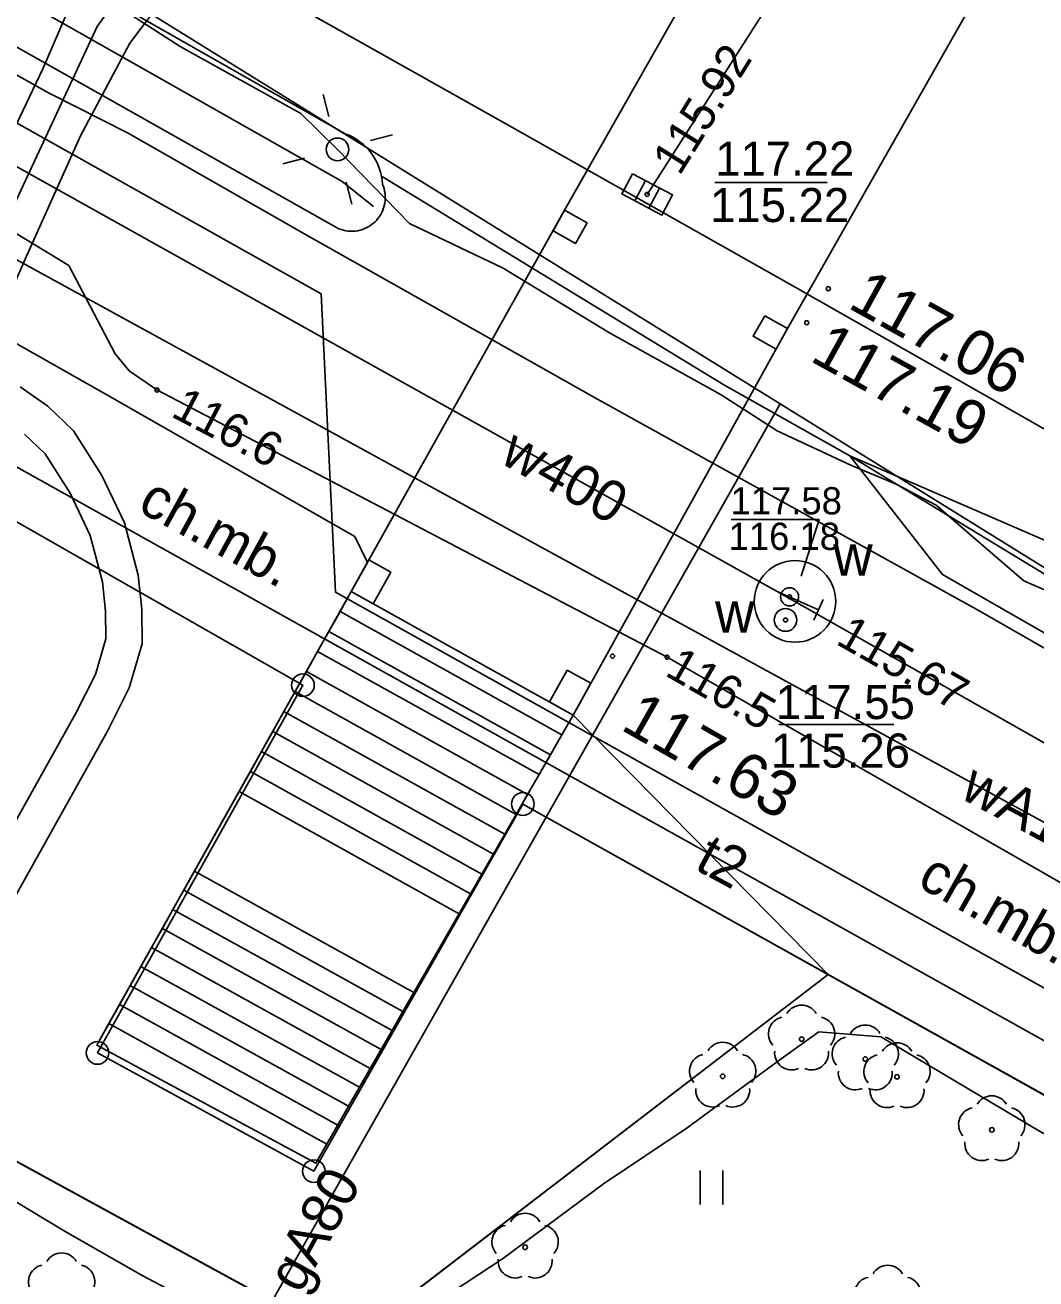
# Model space of a CAD drawing. Extents: x 6434771 to 6436222, y 5663454 to 5664782.
# Drawn here: x 6435235.8 to 6435258.09, y 5663843.93 to 5663871.57 of the extents above; entities that cross this region are included whole.
import ezdxf

# ---------------------------------------------------------------- set-up
doc = ezdxf.new("R2010")
doc.units = 0
for name, color, linetype in [('Warstwa 1', 7, 'Continuous'), ('Warstwa 10', 7, 'Continuous'), ('Warstwa 11', 7, 'Continuous'), ('Warstwa 12', 7, 'Continuous'), ('Warstwa 13', 7, 'Continuous'), ('Warstwa 14', 7, 'Continuous'), ('Warstwa 15', 7, 'Continuous'), ('Warstwa 2', 7, 'Continuous'), ('Warstwa 20', 7, 'Continuous'), ('Warstwa 25', 7, 'Continuous'), ('Warstwa 36', 7, 'Continuous'), ('Warstwa 4', 7, 'Continuous'), ('Warstwa 5', 7, 'Continuous'), ('Warstwa 6', 7, 'Continuous'), ('Warstwa 7', 7, 'Continuous'), ('Warstwa 8', 7, 'Continuous'), ('Warstwa 9', 7, 'Continuous')]:
    doc.layers.add(name, color=color, linetype=linetype)

msp = doc.modelspace()

# ---------------------------------------------------------------- linework, layer by layer
at = {"layer": 'Warstwa 1'}
for p, q in [((6435210.691, 5663874.851), (6435241.929, 5663857.022)), ((6435210.691, 5663874.851), (6435241.929, 5663857.022)), ((6435237.4, 5663848.916), (6435241.929, 5663857.022)), ((6435237.4, 5663848.916), (6435241.929, 5663857.022)), ((6435242.169, 5663846.309), (6435246.778, 5663854.403)), ((6435242.169, 5663846.309), (6435246.778, 5663854.403)), ((6435246.778, 5663854.403), (6435284.269, 5663833.48)), ((6435246.778, 5663854.403), (6435284.269, 5663833.48)), ((6435237.4, 5663848.916), (6435242.169, 5663846.309)), ((6435237.4, 5663848.916), (6435242.169, 5663846.309))]:
    msp.add_line(p, q, dxfattribs=at)
for points in [[(6435247.699, 5663867.491), (6435248.196, 5663867.212), (6435247.942, 5663866.759), (6435247.445, 5663867.037)], [(6435252.112, 5663865.166), (6435252.618, 5663864.883), (6435252.363, 5663864.429), (6435251.857, 5663864.713)], [(6435243.384, 5663859.783), (6435243.865, 5663859.516), (6435243.476, 5663858.817), (6435242.995, 5663859.084)], [(6435247.755, 5663857.355), (6435248.279, 5663857.063), (6435247.89, 5663856.364), (6435247.366, 5663856.655)]]:
    msp.add_lwpolyline(points, close=True, dxfattribs=at)
at = {"layer": 'Warstwa 10'}
for points in [[(6435276.336, 5663842.501), (6435260.05, 5663851.86), (6435249.96, 5663857.64), (6435238.71, 5663863.53), (6435238.1, 5663863.95), (6435237.79, 5663864.33), (6435236.77, 5663866.27), (6435229, 5663870.99), (6435224.85, 5663875.36), (6435224.07, 5663876.18), (6435215.14, 5663881.13), (6435208.14, 5663884.9), (6435192.12, 5663893.65), (6435170.67, 5663905.68), (6435152.15, 5663915.89), (6435146.79, 5663915.59), (6435128.02, 5663926.23), (6435125.23, 5663931.72), (6435111.04, 5663939.84), (6435099.552, 5663946.221)], [(6435276.398, 5663847.572), (6435270.914, 5663850.621), (6435269.128, 5663851.761), (6435267.523, 5663852.588), (6435261.727, 5663855.858), (6435256.855, 5663858.651), (6435248.36, 5663863.366), (6435242.1, 5663866.891), (6435238.077, 5663869.191), (6435236.318, 5663870.082), (6435231.153, 5663872.984), (6435227.254, 5663875.255), (6435219.004, 5663879.813), (6435214.473, 5663882.474), (6435208.6, 5663885.825), (6435204.743, 5663887.86), (6435202.556, 5663889.192), (6435198.825, 5663891.256), (6435191.441, 5663895.523), (6435189.466, 5663896.541), (6435185.427, 5663898.858)]]:
    msp.add_lwpolyline(points, dxfattribs=at)
for centre in [(6435241.929, 5663857.022), (6435241.929, 5663857.022), (6435246.778, 5663854.403), (6435246.778, 5663854.403), (6435237.4, 5663848.916), (6435237.4, 5663848.916), (6435242.169, 5663846.309), (6435242.169, 5663846.309)]:
    msp.add_circle(centre, 0.25, dxfattribs=at)
at = {"layer": 'Warstwa 11'}
for centre in [(6435252.926, 5663849.219), (6435254.33, 5663848.78), (6435251.186, 5663848.4), (6435255.03, 5663848.39), (6435257.12, 5663847.22), (6435246.829, 5663844.632)]:
    msp.add_circle(centre, 0.05, dxfattribs=at)
for centre, start, end in [((6435252.926, 5663849.594), 30.1471, 149.8529), ((6435252.569, 5663849.335), 102.1471, 221.8529), ((6435253.283, 5663849.335), 318.1471, 77.8529), ((6435254.33, 5663849.155), 30.1471, 149.8529), ((6435251.186, 5663848.775), 30.1471, 149.8529), ((6435253.973, 5663848.896), 102.1471, 221.8529), ((6435255.03, 5663848.765), 30.1471, 149.8529), ((6435254.687, 5663848.896), 318.1471, 77.8529), ((6435250.829, 5663848.516), 102.1471, 221.8529), ((6435251.543, 5663848.516), 318.1471, 77.8529), ((6435252.706, 5663848.916), 174.1471, 293.8529), ((6435253.146, 5663848.916), 246.1471, 5.8529), ((6435254.673, 5663848.506), 102.1471, 221.8529), ((6435255.387, 5663848.506), 318.1471, 77.8529), ((6435254.11, 5663848.477), 174.1471, 293.8529), ((6435254.55, 5663848.477), 246.1471, 5.8529), ((6435250.966, 5663848.097), 174.1471, 293.8529), ((6435251.406, 5663848.097), 246.1471, 5.8529), ((6435254.81, 5663848.087), 174.1471, 293.8529), ((6435255.25, 5663848.087), 246.1471, 5.8529), ((6435257.12, 5663847.595), 30.1471, 149.8529), ((6435256.763, 5663847.336), 102.1471, 221.8529), ((6435257.477, 5663847.336), 318.1471, 77.8529), ((6435256.9, 5663846.917), 174.1471, 293.8529), ((6435257.34, 5663846.917), 246.1471, 5.8529), ((6435246.829, 5663845.007), 30.1471, 149.8529), ((6435246.472, 5663844.748), 102.1471, 221.8529), ((6435247.186, 5663844.748), 318.1471, 77.8529), ((6435236.608, 5663844.131), 30.1471, 149.8529), ((6435236.251, 5663843.872), 102.1471, 221.8529), ((6435236.965, 5663843.872), 318.1471, 77.8529), ((6435246.609, 5663844.329), 174.1471, 293.8529), ((6435247.049, 5663844.329), 246.1471, 5.8529), ((6435254.826, 5663843.861), 30.1471, 149.8529), ((6435254.469, 5663843.602), 102.1471, 221.8529), ((6435255.183, 5663843.602), 318.1471, 77.8529)]:
    msp.add_arc(centre, 0.375, start, end, dxfattribs=at)
at = {"layer": 'Warstwa 12'}
for points in [[(6435276.296, 5663839.122), (6435202.248, 5663880.463), (6435193.528, 5663885.439), (6435193.106, 5663885.714), (6435192.653, 5663885.899), (6435159.975, 5663904.455), (6435111.809, 5663931.659), (6435087.394, 5663945.495), (6435086.953, 5663945.766), (6435086.601, 5663946.025), (6435086.024, 5663946.382)], [(6435107.26, 5663946.125), (6435127.986, 5663934.544), (6435149.124, 5663922.599), (6435165.622, 5663913.277), (6435237.784, 5663872.323), (6435252.455, 5663863.225), (6435276.408, 5663848.377)], [(6435246.313, 5663910.094), (6435245.72, 5663909.93), (6435240.9, 5663901.36), (6435226.24, 5663874.68), (6435242.33, 5663865.65), (6435242.65, 5663859.07), (6435272.24, 5663842.55), (6435276.308, 5663840.167)], [(6435256.631, 5663899.106), (6435254.109, 5663895.435), (6435253.432, 5663894.446), (6435252.842, 5663893.524), (6435250.72, 5663890.467), (6435247.918, 5663886.553), (6435245.206, 5663882.627), (6435241.482, 5663877.301), (6435239.483, 5663874.478), (6435237.391, 5663871.54), (6435235.32, 5663867.088), (6435232.38, 5663860.459), (6435228.304, 5663851.592), (6435226.059, 5663846.687), (6435233.662, 5663842.273), (6435239.222, 5663839.112), (6435239.979, 5663838.573), (6435240.755, 5663838.015), (6435243.432, 5663836.474), (6435248.386, 5663833.561), (6435249.655, 5663832.225)], [(6435223.924, 5663873.574), (6435225.447, 5663872.732), (6435231.141, 5663868.843), (6435252.104, 5663857.369), (6435275.75, 5663844.453)], [(6435237.986, 5663871.892), (6435239.219, 5663871.101), (6435241.885, 5663869.623), (6435242.692, 5663868.834), (6435244.278, 5663867.202), (6435246.346, 5663866.214), (6435248.688, 5663864.788), (6435251.155, 5663863.423), (6435252.387, 5663862.631), (6435254.024, 5663861.865), (6435255.012, 5663861.45), (6435255.89, 5663860.989), (6435256.658, 5663860.327), (6435257.826, 5663859.319), (6435258.506, 5663859.031), (6435259.805, 5663858.704), (6435260.919, 5663858.35)], [(6435232.54, 5663865.66), (6435234.09, 5663868.71), (6435234.89, 5663868.85), (6435252.389, 5663859.088), (6435252.78, 5663858.87), (6435276.372, 5663845.49)], [(6435233.809, 5663849.202), (6435237.617, 5663856.012), (6435238.098, 5663856.963), (6435238.387, 5663857.936), (6435238.377, 5663858.699), (6435238.298, 5663859.449), (6435237.993, 5663860.6), (6435237.497, 5663861.645), (6435236.869, 5663862.63), (6435236.301, 5663863.176), (6435235.694, 5663863.596)], [(6435224.443, 5663813.783), (6435252.455, 5663863.225)], [(6435235.793, 5663862.554), (6435236.245, 5663862.12), (6435236.795, 5663861.257), (6435237.239, 5663860.324), (6435237.508, 5663859.303), (6435237.577, 5663858.651), (6435237.585, 5663858.046), (6435237.352, 5663857.259), (6435236.911, 5663856.388), (6435233.111, 5663849.592)], [(6435252.39, 5663859.09), (6435253.3, 5663858.68)], [(6435235.049, 5663845.961), (6435236.683, 5663844.978), (6435238.401, 5663844.001), (6435240.622, 5663842.825), (6435242.5, 5663841.606), (6435243.785, 5663842.585), (6435244.632, 5663843.258), (6435246.33, 5663844.379), (6435248.554, 5663846.03), (6435250.401, 5663847.265), (6435252.476, 5663848.785), (6435253.306, 5663849.381), (6435254.67, 5663849.272), (6435258.169, 5663847.194), (6435259.919, 5663846.249), (6435260.953, 5663845.694), (6435263.079, 5663844.425), (6435264.783, 5663843.511), (6435266.88, 5663842.337), (6435270.04, 5663840.543), (6435272.099, 5663839.408), (6435273.316, 5663838.648), (6435274.936, 5663837.804), (6435276.27, 5663836.996)]]:
    msp.add_lwpolyline(points, dxfattribs=at)
msp.add_lwpolyline([(6435247.89, 5663856.364), (6435242.995, 5663859.084), (6435247.699, 5663867.491), (6435254.05, 5663878.668), (6435260.23, 5663889.971), (6435267.246, 5663902.216), (6435272.128, 5663899.576), (6435265.126, 5663887.191), (6435258.938, 5663876.018), (6435252.618, 5663864.883)], close=True, dxfattribs=at)
at = {"layer": 'Warstwa 14'}
for p, q in [((6435251.014, 5663868.103), (6435253.487, 5663868.103)), ((6435254.959, 5663856.158), (6435252.426, 5663856.158))]:
    msp.add_line(p, q, dxfattribs=at)
msp.add_lwpolyline([(6435252.916, 5663859.423), (6435253.311, 5663860.674), (6435251.374, 5663860.674)], dxfattribs=at)
for centre in [(6435249.521, 5663867.841), (6435249.521, 5663867.841), (6435238.71, 5663863.53), (6435252.66, 5663858.97), (6435252.57, 5663858.46), (6435252.57, 5663858.46), (6435249.96, 5663857.64)]:
    msp.add_circle(centre, 0.045, dxfattribs=at)
at = {"layer": 'Warstwa 15'}
msp.add_circle((6435252.78, 5663858.87), 0.9, dxfattribs=at)
at = {"layer": 'Warstwa 2'}
msp.add_lwpolyline([(6435276.282, 5663837.937), (6435253.515, 5663850.644), (6435242.925, 5663842.53), (6435233.878, 5663847.467), (6435235.268, 5663860.824), (6435230.444, 5663863.459), (6435224.879, 5663866.571), (6435218.959, 5663869.867), (6435212.182, 5663873.589), (6435210.31, 5663874.67)], dxfattribs=at)
msp.add_circle((6435242.692, 5663868.834), 0.25, dxfattribs=at)
at = {"layer": 'Warstwa 20'}
msp.add_line((6435253.403, 5663858.908), (6435253.197, 5663858.452), dxfattribs=at)
at = {"layer": 'Warstwa 25'}
for centre in [(6435253.515, 5663865.762), (6435253.039, 5663865.012), (6435248.756, 5663857.662)]:
    msp.add_circle(centre, 0.045, dxfattribs=at)
at = {"layer": 'Warstwa 36'}
for p, q in [((6435247.638, 5663855.926), (6435242.748, 5663858.644)), ((6435247.387, 5663855.488), (6435242.501, 5663858.203)), ((6435247.135, 5663855.05), (6435242.253, 5663857.763)), ((6435246.883, 5663854.612), (6435242.006, 5663857.323)), ((6435246.631, 5663854.174), (6435241.759, 5663856.882)), ((6435246.379, 5663853.735), (6435241.511, 5663856.441)), ((6435246.128, 5663853.297), (6435241.264, 5663856)), ((6435245.876, 5663852.859), (6435241.017, 5663855.56)), ((6435245.625, 5663852.421), (6435240.77, 5663855.119)), ((6435244.135, 5663849.828), (6435239.3, 5663852.501)), ((6435243.895, 5663849.411), (6435239.064, 5663852.081)), ((6435243.655, 5663848.994), (6435238.829, 5663851.661)), ((6435243.415, 5663848.576), (6435238.593, 5663851.242)), ((6435243.175, 5663848.159), (6435238.358, 5663850.822)), ((6435242.936, 5663847.742), (6435238.122, 5663850.402)), ((6435242.696, 5663847.324), (6435237.887, 5663849.983)), ((6435242.456, 5663846.906), (6435237.651, 5663849.563))]:
    msp.add_line(p, q, dxfattribs=at)
for points in [[(6435242.995, 5663859.084), (6435247.89, 5663856.364), (6435242.216, 5663846.489), (6435237.384, 5663849.087), (6435242.995, 5663859.084)], [(6435240.522, 5663854.679), (6435245.373, 5663851.983)], [(6435239.536, 5663852.921), (6435244.375, 5663850.246)]]:
    msp.add_lwpolyline(points, dxfattribs=at)
at = {"layer": 'Warstwa 4'}
for p, q in [((6435249.483, 5663868.144), (6435249.25, 5663867.702)), ((6435249.792, 5663867.98), (6435249.559, 5663867.538))]:
    msp.add_line(p, q, dxfattribs=at)
for points in [[(6435243.487, 5663867.574), (6435242.798, 5663868.127), (6435217.042, 5663882.709)], [(6435242.5, 5663869.559), (6435242.373, 5663870.043)], [(6435243.417, 5663869.026), (6435243.901, 5663869.153)], [(6435241.967, 5663868.642), (6435241.483, 5663868.515)], [(6435242.884, 5663868.109), (6435243.011, 5663867.625)], [(6435253.991, 5663862.077), (6435258.99, 5663859.046), (6435274.658, 5663850.446), (6435276.421, 5663849.465)]]:
    msp.add_lwpolyline(points, dxfattribs=at)
msp.add_lwpolyline([(6435249.196, 5663868.296), (6435250.08, 5663867.829), (6435249.846, 5663867.386), (6435248.962, 5663867.853)], close=True, dxfattribs=at)
for centre, radius in [((6435252.66, 5663858.97), 0.2), ((6435252.57, 5663858.46), 0.25)]:
    msp.add_circle(centre, radius, dxfattribs=at)
at = {"layer": 'Warstwa 5'}
for p, q in [((6435242.925, 5663842.53), (6435253.515, 5663850.644)), ((6435253.515, 5663850.644), (6435276.282, 5663837.937)), ((6435233.878, 5663847.467), (6435242.925, 5663842.53)), ((6435250.687, 5663845.572), (6435250.687, 5663846.322)), ((6435251.187, 5663845.572), (6435251.187, 5663846.322))]:
    msp.add_line(p, q, dxfattribs=at)
at = {"layer": 'Warstwa 6'}
for points in [[(6435069.683, 5663952.11), (6435199.169, 5663878.85), (6435199.759, 5663878.873), (6435200.658, 5663880.452), (6435202.784, 5663879.266), (6435210.691, 5663874.851), (6435241.929, 5663857.022), (6435237.4, 5663848.916), (6435242.169, 5663846.309), (6435246.778, 5663854.403), (6435284.269, 5663833.48)], [(6435220.804, 5663883.166), (6435221.429, 5663883.018), (6435221.994, 5663882.855), (6435222.535, 5663882.686), (6435223.026, 5663882.511), (6435223.647, 5663882.272), (6435226.004, 5663880.916), (6435234.22, 5663876.266), (6435240.311, 5663872.825), (6435246.65, 5663869.255), (6435252.784, 5663865.794), (6435268.113, 5663857.071), (6435276.455, 5663852.276)], [(6435557.624, 5663617.186), (6435560.245, 5663620.878), (6435595.767, 5663670.923), (6435531.111, 5663701.684), (6435473.15, 5663729.463), (6435470.997, 5663730.839), (6435385.94, 5663776.469), (6435383.505, 5663771.998), (6435381.775, 5663772.849), (6435379.415, 5663768.737), (6435374.588, 5663771.455), (6435379.471, 5663779.947), (6435341.096, 5663801.352), (6435284.269, 5663833.48), (6435246.778, 5663854.403), (6435242.169, 5663846.309), (6435237.4, 5663848.916), (6435241.929, 5663857.022), (6435210.691, 5663874.851), (6435202.784, 5663879.266), (6435199.977, 5663874.56), (6435180.355, 5663839.798)]]:
    msp.add_lwpolyline(points, dxfattribs=at)
for centre in [(6435249.521, 5663867.841), (6435252.66, 5663858.97), (6435252.57, 5663858.46)]:
    msp.add_circle(centre, 0.045, dxfattribs=at)
at = {"layer": 'Warstwa 7'}
msp.add_lwpolyline([(6435249.521, 5663867.841), (6435254.668, 5663875.889)], dxfattribs=at)
at = {"layer": 'Warstwa 8'}
for p, q in [((6435240.311, 5663872.825), (6435246.65, 5663869.255)), ((6435246.65, 5663869.255), (6435252.784, 5663865.794)), ((6435252.784, 5663865.794), (6435268.113, 5663857.071))]:
    msp.add_line(p, q, dxfattribs=at)
for points in [[(6435239.364, 5663872.838), (6435238.113, 5663871.174), (6435237.025, 5663869.134), (6435235.807, 5663866.415), (6435234.445, 5663863.333)], [(6435234.5, 5663867.073), (6435236.194, 5663870.608), (6435236.942, 5663872.353)]]:
    msp.add_lwpolyline(points, dxfattribs=at)
at = {"layer": 'Warstwa 9'}
for p, q in [((6435218.213, 5663883.2), (6435242.876, 5663869.171)), ((6435215.871, 5663882.218), (6435242.721, 5663867.083)), ((6435240.311, 5663872.825), (6435246.65, 5663869.255)), ((6435242.876, 5663869.171), (6435242.96, 5663869.136)), ((6435242.96, 5663869.136), (6435243.041, 5663869.095)), ((6435243.041, 5663869.095), (6435243.118, 5663869.048)), ((6435243.118, 5663869.048), (6435243.192, 5663868.995)), ((6435246.65, 5663869.255), (6435252.784, 5663865.794)), ((6435243.192, 5663868.995), (6435243.262, 5663868.938)), ((6435243.262, 5663868.938), (6435243.328, 5663868.875)), ((6435243.328, 5663868.875), (6435243.389, 5663868.808)), ((6435243.389, 5663868.808), (6435243.445, 5663868.737)), ((6435243.445, 5663868.737), (6435243.496, 5663868.662)), ((6435243.496, 5663868.662), (6435243.541, 5663868.583)), ((6435243.541, 5663868.583), (6435243.58, 5663868.501)), ((6435243.58, 5663868.501), (6435243.613, 5663868.417)), ((6435243.613, 5663868.417), (6435243.64, 5663868.33)), ((6435243.64, 5663868.33), (6435243.661, 5663868.242)), ((6435243.661, 5663868.242), (6435251.211, 5663863.643)), ((6435243.661, 5663868.242), (6435243.676, 5663868.153)), ((6435243.661, 5663868.242), (6435251.211, 5663863.643)), ((6435243.676, 5663868.153), (6435243.683, 5663868.062)), ((6435243.683, 5663868.062), (6435243.703, 5663868.013)), ((6435243.703, 5663868.013), (6435243.718, 5663867.962)), ((6435243.718, 5663867.962), (6435243.73, 5663867.91)), ((6435243.723, 5663867.594), (6435243.734, 5663867.646)), ((6435243.73, 5663867.91), (6435243.739, 5663867.858)), ((6435243.734, 5663867.646), (6435243.741, 5663867.699)), ((6435243.739, 5663867.858), (6435243.743, 5663867.805)), ((6435243.741, 5663867.699), (6435243.744, 5663867.752)), ((6435243.743, 5663867.805), (6435243.744, 5663867.752)), ((6435243.616, 5663867.352), (6435243.644, 5663867.397)), ((6435243.644, 5663867.397), (6435243.669, 5663867.444)), ((6435243.669, 5663867.444), (6435243.691, 5663867.493)), ((6435243.691, 5663867.493), (6435243.709, 5663867.543)), ((6435243.709, 5663867.543), (6435243.723, 5663867.594)), ((6435243.291, 5663867.086), (6435243.339, 5663867.109)), ((6435243.339, 5663867.109), (6435243.386, 5663867.135)), ((6435243.386, 5663867.135), (6435243.43, 5663867.164)), ((6435243.43, 5663867.164), (6435243.473, 5663867.196)), ((6435243.473, 5663867.196), (6435243.513, 5663867.231)), ((6435243.513, 5663867.231), (6435243.55, 5663867.269)), ((6435243.55, 5663867.269), (6435243.584, 5663867.309)), ((6435243.584, 5663867.309), (6435243.616, 5663867.352)), ((6435242.721, 5663867.083), (6435242.771, 5663867.065)), ((6435242.771, 5663867.065), (6435242.822, 5663867.05)), ((6435242.822, 5663867.05), (6435242.874, 5663867.039)), ((6435242.874, 5663867.039), (6435242.927, 5663867.032)), ((6435242.927, 5663867.032), (6435242.98, 5663867.028)), ((6435242.98, 5663867.028), (6435243.033, 5663867.029)), ((6435243.033, 5663867.029), (6435243.086, 5663867.033)), ((6435243.086, 5663867.033), (6435243.139, 5663867.04)), ((6435243.139, 5663867.04), (6435243.191, 5663867.052)), ((6435243.191, 5663867.052), (6435243.242, 5663867.067)), ((6435243.242, 5663867.067), (6435243.291, 5663867.086)), ((6435232.025, 5663866.569), (6435237.504, 5663863.481)), ((6435232.025, 5663866.569), (6435237.504, 5663863.481)), ((6435252.784, 5663865.794), (6435268.113, 5663857.071)), ((6435251.211, 5663863.643), (6435253.991, 5663862.077)), ((6435251.211, 5663863.643), (6435253.991, 5663862.077)), ((6435237.504, 5663863.481), (6435243.071, 5663860.303)), ((6435237.504, 5663863.481), (6435243.071, 5663860.303)), ((6435253.991, 5663862.077), (6435256.03, 5663859.462)), ((6435253.991, 5663862.077), (6435261.95, 5663858.63)), ((6435243.071, 5663860.303), (6435243.355, 5663859.727)), ((6435243.071, 5663860.303), (6435243.355, 5663859.727)), ((6435242.995, 5663859.084), (6435243.355, 5663859.727)), ((6435242.995, 5663859.084), (6435243.355, 5663859.727)), ((6435256.03, 5663859.462), (6435275.377, 5663848.338)), ((6435242.748, 5663858.644), (6435242.995, 5663859.084)), ((6435242.995, 5663859.084), (6435247.89, 5663856.364)), ((6435242.501, 5663858.203), (6435242.748, 5663858.644)), ((6435242.253, 5663857.763), (6435242.501, 5663858.203)), ((6435242.006, 5663857.323), (6435242.253, 5663857.763)), ((6435241.759, 5663856.882), (6435242.006, 5663857.323)), ((6435241.511, 5663856.441), (6435241.759, 5663856.882)), ((6435241.264, 5663856), (6435241.511, 5663856.441)), ((6435247.638, 5663855.926), (6435247.89, 5663856.364)), ((6435247.89, 5663856.364), (6435253.515, 5663850.644)), ((6435247.89, 5663856.364), (6435253.515, 5663850.644)), ((6435241.017, 5663855.56), (6435241.264, 5663856)), ((6435247.387, 5663855.488), (6435247.638, 5663855.926)), ((6435240.77, 5663855.119), (6435241.017, 5663855.56)), ((6435247.135, 5663855.05), (6435247.387, 5663855.488)), ((6435240.522, 5663854.679), (6435240.77, 5663855.119)), ((6435246.883, 5663854.612), (6435247.135, 5663855.05)), ((6435239.536, 5663852.921), (6435240.522, 5663854.679)), ((6435246.631, 5663854.174), (6435246.883, 5663854.612)), ((6435246.379, 5663853.735), (6435246.631, 5663854.174)), ((6435246.128, 5663853.297), (6435246.379, 5663853.735)), ((6435245.876, 5663852.859), (6435246.128, 5663853.297)), ((6435239.3, 5663852.501), (6435239.536, 5663852.921)), ((6435245.625, 5663852.421), (6435245.876, 5663852.859)), ((6435239.064, 5663852.081), (6435239.3, 5663852.501)), ((6435245.373, 5663851.983), (6435245.625, 5663852.421)), ((6435238.829, 5663851.661), (6435239.064, 5663852.081)), ((6435244.375, 5663850.246), (6435245.373, 5663851.983)), ((6435238.593, 5663851.242), (6435238.829, 5663851.661)), ((6435238.358, 5663850.822), (6435238.593, 5663851.242)), ((6435238.122, 5663850.402), (6435238.358, 5663850.822)), ((6435242.925, 5663842.53), (6435253.515, 5663850.644)), ((6435253.515, 5663850.644), (6435276.282, 5663837.937)), ((6435237.887, 5663849.983), (6435238.122, 5663850.402)), ((6435244.135, 5663849.828), (6435244.375, 5663850.246)), ((6435237.651, 5663849.563), (6435237.887, 5663849.983)), ((6435243.895, 5663849.411), (6435244.135, 5663849.828)), ((6435237.384, 5663849.087), (6435237.651, 5663849.563)), ((6435243.655, 5663848.994), (6435243.895, 5663849.411)), ((6435237.384, 5663849.087), (6435242.216, 5663846.489)), ((6435243.415, 5663848.576), (6435243.655, 5663848.994)), ((6435243.175, 5663848.159), (6435243.415, 5663848.576)), ((6435242.936, 5663847.742), (6435243.175, 5663848.159)), ((6435242.696, 5663847.324), (6435242.936, 5663847.742)), ((6435233.878, 5663847.467), (6435242.925, 5663842.53)), ((6435242.456, 5663846.906), (6435242.696, 5663847.324)), ((6435242.216, 5663846.489), (6435242.456, 5663846.906))]:
    msp.add_line(p, q, dxfattribs=at)

# ---------------------------------------------------------------- texts
at = {"layer": 'Warstwa 13'}
for s, rotation, p in [('w400', 330.843, (6435246.236, 5663861.944)), ('wA175', 332.0462, (6435256.381, 5663854.553)), ('t2', 331.5191, (6435250.533, 5663852.984)), ('gA80', 61.1575, (6435241.877, 5663843.585)), ('gA80', 61.1575, (6435241.877, 5663843.585))]:
    msp.add_text(s, height=0.9, rotation=rotation, dxfattribs=at).set_placement(p)
at = {"layer": 'Warstwa 14'}
for s, rotation, p in [('115.92', 58.0865, (6435250.234, 5663868.232)), ('116.6', 332.3671, (6435238.994, 5663862.958)), ('115.67', 330.4419, (6435253.652, 5663857.945)), ('116.5', 330.1956, (6435249.886, 5663857.25))]:
    msp.add_text(s, height=0.75, rotation=rotation, dxfattribs=at).set_placement(p)
for s, height, p in [('115.22', 0.75, (6435250.908, 5663867.231)), ('116.18', 0.6, (6435251.317, 5663860.004)), ('115.26', 0.75, (6435252.248, 5663855.206))]:
    msp.add_text(s, height=height, dxfattribs=at).set_placement(p)
at = {"layer": 'Warstwa 25'}
for s, rotation, p in [('117.06', 331.0493, (6435253.918, 5663865.354)), ('117.19', 331.0493, (6435253.083, 5663864.184)), ('117.63', 330.3961, (6435248.908, 5663856.056))]:
    msp.add_text(s, height=1, rotation=rotation, dxfattribs=at).set_placement(p)
at = {"layer": 'Warstwa 5'}
for p in [(6435253.624, 5663859.436), (6435251.017, 5663858.177)]:
    msp.add_text('w', height=0.9, dxfattribs=at).set_placement(p)
at = {"layer": 'Warstwa 6'}
for s, height, p in [('117.22', 0.75, (6435251.021, 5663868.256)), ('117.58', 0.6, (6435251.36, 5663860.787)), ('117.55', 0.75, (6435252.356, 5663856.275))]:
    msp.add_text(s, height=height, dxfattribs=at).set_placement(p)
at = {"layer": 'Warstwa 9'}
for rotation, p in [(331.353, (6435238.252, 5663860.879)), (330.4821, (6435255.443, 5663852.61))]:
    msp.add_text('ch.mb.', height=0.9, rotation=rotation, dxfattribs=at).set_placement(p)

doc.saveas('drawing.dxf')
